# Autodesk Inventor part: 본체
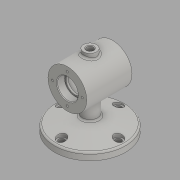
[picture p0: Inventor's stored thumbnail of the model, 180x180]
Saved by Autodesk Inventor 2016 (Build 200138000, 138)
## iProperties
Created: 2018-12
Part Number: 본체
Material: 일반
Document SubType Name: Modeling
Designer: 605-11
Density: 1 g/cm^3
Appearance: 기본값
Author: 605-11
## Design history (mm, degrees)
sketch "스케치1"
  geometry: L1 (-35, 0)-(35, 0); L2 (-35, 0)-(-35, 30); L3 (-35, 30)-(35, 30); L4 (35, 30)-(35, 0); L5 (-35, 16)-(-23, 16); L6 (-23, 16)-(-23, 14); L7 (-23, 14)-(-20, 14); L8 (-20, 14)-(-20, 25); L9 (-20, 25)-(20, 25); L10 (20, 25)-(20, 14); L11 (20, 14)-(23, 14); L12 (23, 14)-(23, 16); L13 (23, 16)-(35, 16); 2 further points
  constraints: 26 end point, 8 perpendicular, 6 point on line, 2 horizontal, 1 coincident, 1 midpoint, 1 vertical
  dimensions: "d0" = 32 diameter of L5 L1; "d1" = 28 diameter of L7 L1; "d2" = 60 diameter of L3 L1; "d3" = 50 diameter of L9 L1; "d4" = 12 distance of L5.start L5.end; "d5" = 3 distance of L6.end L7.end; "d6" = 70 distance of L2.end L3.end; "d7" = 12 distance of L12.end L13.end; "d8" = 40 distance of L8.end L9.end
revolve "회전1" sketch "스케치1" stored, may be unused: angle "d9" = 90 deg
sketch "스케치2" dims "d10" = 46
  geometry: L1 (0, 0)-(23, 0); 2 further points
  constraints: 2 coincident, 2 end point, 1 horizontal, 1 horizontal alignment, 2 other
hole "구멍1" sketch "스케치2" at (23, 0) diameter "d11" = 3.242; stored, may be unused: countersink angle "d15" = 90 deg, drill point angle "d17" = 118 deg; dims "d12" = 8, "d13" = 4, "d14" = 2, "d16" = 10
node "작업 평면1"
sketch "스케치3"
  geometry: C1 r 10 at (0, 0); 1 further point
  constraints: 1 centre point, 1 coincident
  dimensions: "d22" = 20 diameter of C1
extrude "돌출1" join sketch "스케치3" stored distance "d23" = 10; taper "d24" = 0 deg
sketch "스케치4"
  geometry: C1 r 5 at (0, 0); 1 further point
  constraints: 1 centre point, 1 coincident
  dimensions: "d25" = 10 diameter of C1
extrude "돌출2" cut sketch "스케치4" stored distance "d26" = 10; taper "d27" = 0 deg
chamfer "모따기1" distance "d28" = 1; stored, may be unused: second distance "d29" = 2, angle "d30" = 45 deg
fillet "모깎기1" dims "d31" = 3, "d32" = 0.3
node "작업 평면2"
sketch "스케치5"
  geometry: C1 r 55 at (0, 0); 1 further point
  constraints: 1 centre point, 1 coincident
  dimensions: "d34" = 110 diameter of C1
extrude "돌출3" join sketch "스케치5" distance "d35" = 11; taper "d36" = 0 deg
sketch "스케치6"
  geometry: C1 r 12 at (0, 0); 1 further point
  constraints: 1 centre point, 1 coincident
  dimensions: "d37" = 24 diameter of C1
extrude "돌출4" join sketch "스케치6" stored distance "d38" = 11; taper "d39" = 0 deg
sketch "스케치7"
  geometry: L1 (-24.026, 23)-(-25, 24.621) reference; L2 (-25, 24.621)-(-35, 24.621) reference; L3 (-35, 24.621)-(-35, 30) reference; L4 (-35, 30)-(-10, 30) reference; L5 (-10, 30)-(-10, 37) reference; L6 (-10, 37)-(-6, 37) reference; L7 (-6, 37)-(-5, 36) reference; L8 (-5, 36)-(-5, 25) reference; L9 (-5, 25)-(-17, 25) reference; L10 (-20, 22)-(-20, 14) reference; L11 (-20, 14)-(-23, 14) reference; L12 (-23, 14)-(-23, 15.7) reference; L13 (-23.3, 16)-(-34, 16) reference; L14 (-34, 16)-(-35, 17) reference; L15 (-35, 17)-(-35, 21.379) reference; L16 (-35, 21.379)-(-25, 21.379) reference; L17 (-25, 21.379)-(-24.026, 23) reference; L18 (24.026, -23)-(25, -24.621) reference; L19 (25, -24.621)-(35, -24.621) reference; L20 (35, -24.621)-(35, -30) reference; L21 (35, -30)-(12, -30) reference; L22 (12, -30)-(12, -64) reference; L23 (12, -64)-(55, -64) reference; L24 (55, -64)-(55, -75) reference; L25 (55, -75)-(-55, -75) reference; L26 (-55, -75)-(-55, -64) reference; L27 (-55, -64)-(-12, -64) reference; L28 (-12, -64)-(-12, -30) reference; L29 (-12, -30)-(-35, -30) reference; L30 (-35, -30)-(-35, -24.621) reference; L31 (-35, -24.621)-(-25, -24.621) reference; L32 (-25, -24.621)-(-24.026, -23) reference; L33 (-24.026, -23)-(-25, -21.379) reference; L34 (-25, -21.379)-(-35, -21.379) reference; L35 (-35, -21.379)-(-35, -17) reference; L36 (-35, -17)-(-34, -16) reference; L37 (-34, -16)-(-23.3, -16) reference; L38 (-23, -15.7)-(-23, -14) reference; L39 (-23, -14)-(-20, -14) reference; L40 (-20, -14)-(-20, -22) reference; L41 (-17, -25)-(17, -25) reference; L42 (20, -22)-(20, -14) reference; L43 (20, -14)-(23, -14) reference; L44 (23, -14)-(23, -15.7) reference; L45 (23.3, -16)-(34, -16) reference; L46 (34, -16)-(35, -17) reference; L47 (35, -17)-(35, -21.379) reference; L48 (35, -21.379)-(25, -21.379) reference; L49 (25, -21.379)-(24.026, -23) reference; L50 (25, 24.621)-(24.026, 23) reference; L51 (24.026, 23)-(25, 21.379) reference; L52 (25, 21.379)-(35, 21.379) reference; L53 (35, 21.379)-(35, 17) reference; L54 (35, 17)-(34, 16) reference; L55 (34, 16)-(23.3, 16) reference; L56 (23, 15.7)-(23, 14) reference; L57 (23, 14)-(20, 14) reference; L58 (20, 14)-(20, 22) reference; L59 (17, 25)-(5, 25) reference; L60 (5, 25)-(5, 36) reference; L61 (5, 36)-(6, 37) reference; L62 (6, 37)-(10, 37) reference; L63 (10, 37)-(10, 30) reference; L64 (10, 30)-(35, 30) reference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; A1 r 3 centre (-17, 22) between (-17, 25) and (-20, 22) reference; A2 r 0.3 centre (-23.3, 15.7) between (-23, 15.7) and (-23.3, 16) reference; A3 r 0.3 centre (-23.3, -15.7) between (-23.3, -16) and (-23, -15.7) reference; A4 r 3 centre (-17, -22) between (-20, -22) and (-17, -25) reference; A5 r 3 centre (17, -22) between (17, -25) and (20, -22) reference; A6 r 0.3 centre (23.3, -15.7) between (23, -15.7) and (23.3, -16) reference; A7 r 0.3 centre (23.3, 15.7) between (23.3, 16) and (23, 15.7) reference; A8 r 3 centre (17, 22) between (20, 22) and (17, 25) reference
  constraints: 4 end point, 1 midpoint, 1 point on line
  dimensions: "d40" = 75 deg angle of L24 L67
revolve "회전2" sketch "스케치7" stored, may be unused: angle "d41" = 90 deg
fillet "모깎기2" dims "d42" = 3
sketch "스케치8" dims "d43" = 88
  geometry: L1 (0, 0)-(44, 0); 2 further points
  constraints: 2 coincident, 2 end point, 1 horizontal, 1 horizontal alignment, 2 other
hole "구멍2" sketch "스케치8" at (44, 0) diameter "d44" = 9; stored, may be unused: countersink angle "d48" = 90 deg, drill point angle "d50" = 118 deg; dims "d45" = 6, "d46" = 4, "d47" = 2, "d49" = 10
node "작업 평면3"
sketch "스케치9" dims "d52" = 88
  geometry: L1 (0, 0)-(44, 0); C1 r 14.224 at (0, 0) reference; C2 r 52.776 at (0, 0) reference; C3 r 7 at (44, 0); 4 further points
  constraints: 2 coincident, 2 end point, 1 centre point, 1 horizontal, 1 horizontal alignment, 4 other
  dimensions: "d53" = 14 diameter of C3
extrude "돌출5" cut sketch "스케치9" stored distance "d54" = 10; taper "d55" = 0 deg
node "솔리드1"
pattern_circular "원형 패턴1" dims angle "d19" = 360 deg
mirror "대칭1"
pattern_circular "원형 패턴2" dims angle "d57" = 360 deg
node "투영된 루프1"
node "절단 모서리 투영1"
other parameters: "d21" = 37, "d33" = -75
